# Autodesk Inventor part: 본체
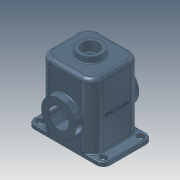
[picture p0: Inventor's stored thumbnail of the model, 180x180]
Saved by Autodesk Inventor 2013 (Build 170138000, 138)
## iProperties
Company: 한국ATC센터
Created: 2014-10
Part Number: 본체
Document SubType Name: Modeling
Designer: 한국ATC센터
Density: 7.86 g/cm^3
Material: 강철, 연강
Mass: 9529.05 g
Surface Area: 2358.48 cm^2
Volume: 1212.35 cm^3
Author: KYOUNG IL JANG
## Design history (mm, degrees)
sketch "스케치1"
  geometry: L1 (-70, 65)-(70, 65); L2 (70, 65)-(70, -65); L3 (70, -65)-(-70, -65); L4 (-70, -65)-(-70, 65); 3 further points
  constraints: 8 end point, 2 midpoint, 2 parallel, 1 horizontal, 1 horizontal alignment, 1 perpendicular, 1 vertical alignment
  dimensions: "d0" = 140 distance of L2.end L3.end; "d68" = 130 distance of L3.end L1.start
extrude "돌출1" new body sketch "스케치1" distance "d1" = 180; taper "d2" = 0 deg
fillet "모깎기1" dims "d3" = 20
feature "쉘1" dims "d4" = 10
sketch "스케치2"
  geometry: L1 (-70, 45)-(-70, -45) reference; L2 (-50, -65)-(-82, -65); L3 (-82, 65)-(-50, 65); L4 (-85, 57)-(-82, 57); L5 (-82, 41)-(-85, 41); L6 (-100, 47)-(-100, -47); A1 r 20 centre (-50, 45) between (-50, 65) and (-70, 45) reference; A2 r 20 centre (-50, -45) between (-70, -45) and (-50, -65) reference; A3 r 8 centre (-82, 49) between (-82, 41) and (-82, 57); A4 r 8 centre (-85, 49) between (-85, 57) and (-85, 41); A5 r 18 centre (-82, 47) between (-82, 65) and (-100, 47); A6 r 18 centre (-82, -47) between (-100, -47) and (-82, -65); 1 further point
  constraints: 10 end point, 9 tangent, 8 point on circle, 4 centre point, 2 parallel, 2 perpendicular, 1 equal radius
  dimensions: "d6" = 49 vertical distance of point (0, 0) A3.centre; "d8" = 16 distance between parallel lines of L4 L5; "d64" = 18 radius of A5; "d65" = 12 distance from line of A3.centre L1; "d66" = 30 distance between parallel lines of L6 L1; "d67" = 3 distance of A4.centre A3.centre
extrude "돌출2" join sketch "스케치2" distance "d9" = 10; taper "d10" = 0 deg
extrude "돌출3" cut sketch "스케치2" stored distance "d11" = 10; taper "d12" = 0 deg
sketch "스케치3"
  geometry: L1 (-65, 0)-(-65, 180) reference; L2 (-55, 0)-(-55, 170) reference; L3 (-83, 75)-(-51, 75); L4 (45, 0)-(-45, 0) reference; L5 (-83, 75)-(-83, 120.5); L6 (-83, 120.5)-(-55, 120.5); L7 (-55, 120.5)-(-51, 116.5); L8 (-51, 116.5)-(-51, 75); 2 further points
  constraints: 10 end point, 4 perpendicular, 1 point on line
  dimensions: "d13" = 75 distance between parallel lines of L3 L4; "d14" = 18 distance from line of L1 L3.start; "d15" = 4 distance from line of L3.end L2; "d16" = 91 diameter of L6 L3; "d17" = 135 deg angle of L7 L2
revolve "회전1" sketch "스케치3" stored, may be unused: angle "d18" = 90 deg
sketch "스케치4"
  geometry: C1 r 45.5 at (0, 0) reference; 2 further points
  constraints: 1 vertical alignment
  dimensions: "d19" = 35 distance of C1.centre point (0, 35)
hole "구멍1" sketch "스케치4" at (0, 35) diameter "d20" = 3.459; stored, may be unused: countersink angle "d24" = 90 deg, drill point angle "d26" = 118 deg; dims "d21" = 13, "d22" = 4, "d23" = 2, "d25" = 16
fillet "모깎기2" dims "d30" = 3
hole "구멍2" diameter "d33" = 52; stored, may be unused: countersink angle "d37" = 90 deg, drill point angle "d39" = 118 deg; dims "d31" = 10, "d32" = 10, "d34" = 13, "d35" = 4, "d36" = 2, "d38" = 16
sketch "스케치5"
  geometry: C1 r 31 at (0, 0); 1 further point
  constraints: 1 centre point, 1 coincident
  dimensions: "d40" = 62 diameter of C1
extrude "돌출4" join sketch "스케치5" distance "d41" = 15; taper "d42" = 0 deg
hole "구멍3" diameter "d45" = 43; stored, may be unused: countersink angle "d49" = 90 deg, drill point angle "d51" = 118 deg; dims "d43" = 10, "d44" = 10, "d46" = 13, "d47" = 4, "d48" = 2, "d50" = 16
fillet "모깎기3" dims "d52" = 3
fillet "모깎기4" dims "d53" = 3
chamfer "모따기1" distance "d55" = 1; stored, may be unused: second distance "d56" = 2, angle "d57" = 45 deg
sketch "스케치6"
  geometry: 2 further points
  constraints: 1 vertical alignment, 1 other
  dimensions: "d71" = 90 distance of point (0, 0) point (0, 90)
feature "엠보싱2" sketch "스케치6" dims "d0" = 140, "d68" = 130, "d72" = 1, "d73" = 0
fillet "모깎기6" dims "d74" = 10
sketch "스케치7"
  geometry: C1 r 15 at (0, 0); C2 r 21.5 at (0, 0) reference; C3 r 25 at (0, 0); 1 further point
  constraints: 2 centre point, 2 coincident
  dimensions: "d61" = 30 diameter of C1; "d75" = 50 diameter of C3
extrude "돌출5" join sketch "스케치7" distance "d62" = 10; taper "d63" = 0 deg
feature "면 이동1" dims "d76" = 1
fillet "모깎기7" dims "d77" = 3
node "솔리드1"
mirror "대칭1"
mirror "대칭2"
pattern_circular "원형 패턴1" dims angle "d28" = 360 deg
mirror "대칭3"
